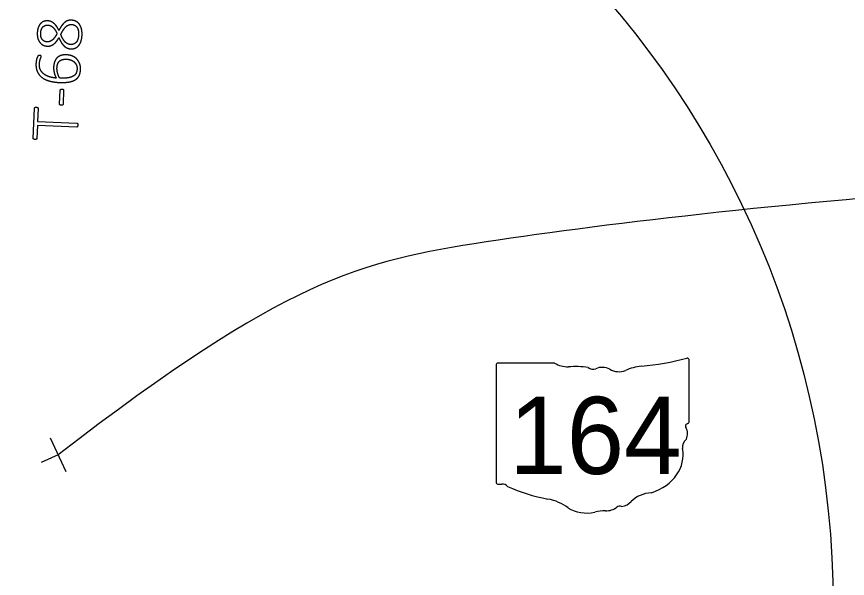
# Model space of a CAD drawing. Extents: x 0 to 1214, y 0 to 883.
# Drawn here: x 200.8 to 281.4, y 330.8 to 385.4 of the extents above; entities that cross this region are included whole.
import ezdxf

# ---------------------------------------------------------------- set-up
doc = ezdxf.new("R2010")
doc.units = 0
for name, color, linetype in [('GM_X_Minor_River', 7, 'Continuous'), ('GM_X_Township_Road_Text', 7, 'Continuous'), ('GM_X_Unincorporated_Location', 7, 'Continuous'), ('SH_Data', 7, 'Continuous')]:
    doc.layers.add(name, color=color, linetype=linetype)

msp = doc.modelspace()

# ---------------------------------------------------------------- linework, layer by layer
at = {"layer": 'GM_X_Minor_River'}
for p, q in [((204.05, 344.481), (205.564, 341.215)), ((204.807, 342.848), (203.174, 342.09))]:
    msp.add_line(p, q, dxfattribs=at)
at = {"layer": 'GM_X_Township_Road_Text'}
for p, q in [((253.012, 351.755), (247.521, 351.755)), ((266.086, 346.082), (266.086, 352.037)), ((247.336, 351.559), (247.336, 340.174)), ((266.084, 346.083), (266.086, 346.082))]:
    msp.add_line(p, q, dxfattribs=at)
for centre, major_axis, start_param, end_param in [((247.551, 351.583), (0.217, 0), 1.712693, 3.28349), ((254.32, 353.076), (2.107, 0), 4.042523, 4.731795), ((259.407, 367.276), (19.884, 0), 4.814394, 5.042369), ((265.878, 352.062), (0.209, 0), 6.141152, 7.989035), ((255.018, 345.363), (7.564, 0), 1.404758, 1.657858), ((256.735, 351.642), (0.608, 0), 3.836095, 5.185415), ((257.627, 350.326), (1.264, 0), 0.950623, 2.079405), ((259.259, 352.131), (1.52, 0), 4.081561, 5.145723), ((261.943, 348.278), (4, 0), 1.699011, 2.107814), ((265.863, 346.059), (0.223, 0), 5.05454, 6.418171), ((266.038, 345.644), (0.323, 0), 1.883978, 3.671073), ((263.983, 344.892), (1.939, 0), 5.934695, 6.695948), ((266.834, 343.589), (1.411, 0), 2.387724, 3.262537), ((260.521, 342.832), (4.973, 0), 5.101752, 6.440018), ((247.553, 340.149), (0.219, 0), 3.00124, 4.508301), ((247.586, 341.314), (1.672, 0), 4.665946, 4.897461), ((247.928, 339.518), (0.603, 0), 0.519207, 1.627899), ((255.542, 349.746), (14.359, 0), 4.195997, 4.488961), ((262.618, 336.978), (2.724, 0), 1.647645, 2.488434), ((251.261, 335.06), (4.493, 0), 0.823519, 1.323587), ((259.167, 339.071), (1.607, 0), 4.937069, 5.64225), ((256.12, 339.461), (2.851, 0), 4.026481, 4.996735), ((257.767, 335.525), (2.342, 0), 1.495662, 1.94098), ((257.975, 338.608), (1.519, 0), 4.691044, 5.507374), ((259.349, 337.506), (0.428, 0), 1.147584, 2.315152)]:
    msp.add_ellipse(centre, major_axis=major_axis, ratio=0.8, start_param=start_param, end_param=end_param, dxfattribs=at)
at = {"layer": 'GM_X_Unincorporated_Location'}
for p, q in [((206.075, 385.079), (206.075, 385.079)), ((203.814, 384.601), (203.814, 384.601)), ((206.114, 384.657), (206.114, 384.657)), ((205.638, 381.71), (205.638, 381.71)), ((205.659, 381.288), (205.659, 381.288)), ((205.183, 378.377), (205.183, 378.377)), ((204.955, 376.916), (205.015, 378.29)), ((205.342, 378.275), (205.282, 376.902)), ((202.39, 373.595), (202.519, 376.526)), ((202.706, 376.619), (202.706, 376.619))]:
    msp.add_line(p, q, dxfattribs=at)
for points in [[(202.874, 376.51), (202.819, 375.245), (206.635, 375.078)], [(206.618, 374.678), (202.802, 374.845), (202.746, 373.579)]]:
    msp.add_lwpolyline(points, dxfattribs=at)
for points in [[(203.421, 384.959), (203.245, 384.894), (203.107, 384.752)], [(203.788, 385.015), (203.598, 385.023), (203.421, 384.959)], [(204.121, 384.941), (203.965, 385.007), (203.788, 385.015)], [(204.413, 384.758), (204.277, 384.875), (204.121, 384.941)], [(205.419, 384.842), (205.274, 384.717), (205.143, 384.527)], [(205.724, 385.027), (205.564, 384.967), (205.419, 384.842)], [(206.075, 385.079), (205.885, 385.087), (205.724, 385.027)], [(206.547, 384.962), (206.343, 385.067), (206.075, 385.079)], [(206.885, 384.668), (206.751, 384.856), (206.547, 384.962)], [(202.883, 384.389), (202.796, 384.168), (202.783, 383.864)], [(203.107, 384.752), (202.97, 384.611), (202.883, 384.389)], [(203.117, 383.813), (203.126, 384.006), (203.178, 384.157)], [(203.178, 384.157), (203.231, 384.308), (203.322, 384.409)], [(203.322, 384.409), (203.413, 384.51), (203.538, 384.559)], [(203.538, 384.559), (203.663, 384.608), (203.814, 384.601)], [(203.814, 384.601), (204.092, 384.589), (204.313, 384.375)], [(204.313, 384.375), (204.535, 384.162), (204.702, 383.776)], [(204.665, 384.472), (204.549, 384.64), (204.413, 384.758)], [(204.88, 384.09), (204.781, 384.305), (204.665, 384.472)], [(205.143, 384.527), (205.012, 384.337), (204.88, 384.09)], [(205.062, 383.692), (205.195, 383.939), (205.312, 384.124)], [(205.312, 384.124), (205.43, 384.309), (205.552, 384.43)], [(205.552, 384.43), (205.674, 384.551), (205.811, 384.608)], [(205.811, 384.608), (205.947, 384.664), (206.114, 384.657)], [(206.114, 384.657), (206.448, 384.642), (206.632, 384.39)], [(206.632, 384.39), (206.816, 384.137), (206.795, 383.665)], [(207.082, 384.214), (207.02, 384.48), (206.885, 384.668)], [(207.13, 383.615), (207.144, 383.949), (207.082, 384.214)], [(202.783, 383.864), (202.769, 383.539), (202.842, 383.296)], [(202.842, 383.296), (202.915, 383.053), (203.051, 382.893)], [(203.269, 383.2), (203.1, 383.416), (203.117, 383.813)], [(203.749, 382.97), (203.438, 382.983), (203.269, 383.2)], [(204.474, 383.407), (204.364, 383.252), (204.25, 383.153)], [(204.702, 383.776), (204.584, 383.561), (204.474, 383.407)], [(204.645, 383.012), (204.77, 383.169), (204.885, 383.378)], [(204.885, 383.378), (204.989, 383.133), (205.103, 382.936)], [(205.269, 383.269), (205.167, 383.451), (205.062, 383.692)], [(205.483, 382.968), (205.37, 383.087), (205.269, 383.269)], [(206.795, 383.665), (206.774, 383.177), (206.569, 382.938)], [(207.038, 383.054), (207.116, 383.303), (207.13, 383.615)], [(203.051, 382.893), (203.186, 382.733), (203.37, 382.649)], [(203.37, 382.649), (203.553, 382.566), (203.759, 382.557)], [(204.013, 383.009), (203.89, 382.964), (203.749, 382.97)], [(203.759, 382.557), (203.933, 382.549), (204.088, 382.598)], [(204.25, 383.153), (204.136, 383.055), (204.013, 383.009)], [(204.088, 382.598), (204.242, 382.647), (204.381, 382.751)], [(204.381, 382.751), (204.52, 382.855), (204.645, 383.012)], [(205.103, 382.936), (205.218, 382.739), (205.356, 382.6)], [(205.356, 382.6), (205.494, 382.461), (205.663, 382.382)], [(205.724, 382.785), (205.596, 382.848), (205.483, 382.968)], [(205.663, 382.382), (205.832, 382.302), (206.042, 382.293)], [(206.013, 382.715), (205.853, 382.722), (205.724, 382.785)], [(206.569, 382.938), (206.363, 382.699), (206.013, 382.715)], [(206.042, 382.293), (206.29, 382.282), (206.486, 382.37)], [(206.486, 382.37), (206.682, 382.459), (206.821, 382.632)], [(206.821, 382.632), (206.96, 382.804), (207.038, 383.054)], [(202.841, 381.589), (202.822, 381.567), (202.789, 381.498)], [(202.879, 381.621), (202.86, 381.612), (202.841, 381.589)], [(202.917, 381.635), (202.897, 381.63), (202.879, 381.621)], [(202.962, 381.643), (202.937, 381.641), (202.917, 381.635)], [(203.02, 381.644), (202.987, 381.645), (202.962, 381.643)], [(203.085, 381.639), (203.056, 381.642), (203.02, 381.644)], [(203.134, 381.628), (203.115, 381.637), (203.085, 381.639)], [(203.164, 381.602), (203.153, 381.618), (203.134, 381.628)], [(203.147, 381.463), (203.172, 381.523), (203.174, 381.559)], [(203.174, 381.559), (203.175, 381.585), (203.164, 381.602)], [(205.165, 381.67), (204.941, 381.619), (204.769, 381.482)], [(205.638, 381.71), (205.389, 381.721), (205.165, 381.67)], [(206.142, 381.609), (205.894, 381.699), (205.638, 381.71)], [(206.582, 381.341), (206.391, 381.519), (206.142, 381.609)], [(202.656, 380.863), (202.641, 380.519), (202.723, 380.253)], [(202.681, 381.104), (202.661, 380.984), (202.656, 380.863)], [(202.729, 381.327), (202.701, 381.225), (202.681, 381.104)], [(202.789, 381.498), (202.757, 381.429), (202.729, 381.327)], [(203.102, 380.226), (202.975, 380.469), (202.99, 380.799)], [(202.99, 380.799), (202.997, 380.973), (203.026, 381.099)], [(203.026, 381.099), (203.054, 381.226), (203.088, 381.315)], [(203.088, 381.315), (203.121, 381.403), (203.147, 381.463)], [(204.492, 381.111), (204.387, 380.876), (204.371, 380.519)], [(204.769, 381.482), (204.598, 381.345), (204.492, 381.111)], [(204.697, 380.455), (204.708, 380.704), (204.782, 380.87)], [(204.782, 380.87), (204.857, 381.035), (204.982, 381.131)], [(204.982, 381.131), (205.108, 381.227), (205.281, 381.262)], [(205.281, 381.262), (205.453, 381.297), (205.659, 381.288)], [(205.659, 381.288), (205.837, 381.281), (206.016, 381.219)], [(206.016, 381.219), (206.196, 381.157), (206.34, 381.036)], [(206.34, 381.036), (206.484, 380.915), (206.57, 380.734)], [(206.886, 380.889), (206.773, 381.162), (206.582, 381.341)], [(206.982, 380.241), (206.999, 380.617), (206.886, 380.889)], [(202.723, 380.253), (202.805, 379.987), (202.959, 379.787)], [(203.455, 379.818), (203.229, 379.982), (203.102, 380.226)], [(204.371, 380.519), (204.364, 380.352), (204.383, 380.201)], [(204.383, 380.201), (204.403, 380.049), (204.438, 379.913)], [(204.709, 380.178), (204.691, 380.318), (204.697, 380.455)], [(204.765, 379.907), (204.728, 380.038), (204.709, 380.178)], [(206.645, 380.311), (206.635, 380.079), (206.544, 379.908)], [(206.57, 380.734), (206.656, 380.553), (206.645, 380.311)], [(206.899, 379.802), (206.971, 379.992), (206.982, 380.241)], [(202.959, 379.787), (203.112, 379.587), (203.33, 379.448)], [(203.33, 379.448), (203.547, 379.309), (203.801, 379.219)], [(203.982, 379.566), (203.681, 379.654), (203.455, 379.818)], [(203.801, 379.219), (204.054, 379.129), (204.336, 379.084)], [(204.617, 379.453), (204.283, 379.477), (203.982, 379.566)], [(204.438, 379.913), (204.473, 379.777), (204.521, 379.662)], [(204.521, 379.662), (204.568, 379.547), (204.617, 379.453)], [(204.854, 379.657), (204.802, 379.776), (204.765, 379.907)], [(204.968, 379.444), (204.906, 379.539), (204.854, 379.657)], [(205.743, 379.471), (205.427, 379.424), (204.968, 379.444)], [(206.255, 379.627), (206.058, 379.518), (205.743, 379.471)], [(205.987, 379.097), (206.216, 379.149), (206.395, 379.24)], [(206.544, 379.908), (206.452, 379.736), (206.255, 379.627)], [(206.395, 379.24), (206.575, 379.331), (206.701, 379.471)], [(206.701, 379.471), (206.827, 379.611), (206.899, 379.802)], [(204.336, 379.084), (204.618, 379.039), (204.9, 379.027)], [(204.9, 379.027), (205.215, 379.013), (205.486, 379.029)], [(205.015, 378.29), (205.016, 378.309), (205.024, 378.327)], [(205.024, 378.327), (205.033, 378.345), (205.054, 378.357)], [(205.054, 378.357), (205.074, 378.369), (205.105, 378.374)], [(205.105, 378.374), (205.137, 378.379), (205.183, 378.377)], [(205.183, 378.377), (205.278, 378.373), (205.311, 378.346)], [(205.311, 378.346), (205.344, 378.318), (205.342, 378.275)], [(205.486, 379.029), (205.758, 379.045), (205.987, 379.097)], [(204.988, 376.844), (204.953, 376.873), (204.955, 376.916)], [(205.114, 376.81), (205.022, 376.814), (204.988, 376.844)], [(205.243, 376.833), (205.206, 376.806), (205.114, 376.81)], [(205.282, 376.902), (205.281, 376.859), (205.243, 376.833)], [(202.519, 376.526), (202.52, 376.549), (202.532, 376.568)], [(202.532, 376.568), (202.544, 376.587), (202.567, 376.599)], [(202.567, 376.599), (202.591, 376.611), (202.625, 376.616)], [(202.625, 376.616), (202.66, 376.621), (202.706, 376.619)], [(202.706, 376.619), (202.748, 376.617), (202.781, 376.609)], [(202.781, 376.609), (202.813, 376.601), (202.834, 376.587)], [(202.834, 376.587), (202.854, 376.573), (202.865, 376.553)], [(202.865, 376.553), (202.875, 376.533), (202.874, 376.51)], [(206.654, 374.686), (206.638, 374.677), (206.618, 374.678)], [(206.635, 375.078), (206.655, 375.077), (206.671, 375.066)], [(206.682, 374.718), (206.671, 374.695), (206.654, 374.686)], [(206.671, 375.066), (206.687, 375.056), (206.696, 375.033)], [(206.701, 374.779), (206.693, 374.74), (206.682, 374.718)], [(206.696, 375.033), (206.705, 375.009), (206.709, 374.97)], [(206.712, 374.874), (206.709, 374.819), (206.701, 374.779)], [(206.709, 374.97), (206.714, 374.93), (206.712, 374.874)], [(202.4, 373.55), (202.389, 373.569), (202.39, 373.595)], [(202.433, 373.517), (202.411, 373.532), (202.4, 373.55)], [(202.489, 373.495), (202.455, 373.503), (202.433, 373.517)], [(202.569, 373.485), (202.523, 373.487), (202.489, 373.495)], [(202.644, 373.489), (202.611, 373.483), (202.569, 373.485)], [(202.699, 373.506), (202.677, 373.494), (202.644, 373.489)], [(202.733, 373.536), (202.721, 373.518), (202.699, 373.506)], [(202.746, 373.579), (202.745, 373.553), (202.733, 373.536)]]:
    msp.add_open_spline(points, degree=2, dxfattribs=at)
at = {"layer": 'SH_Data'}
msp.add_circle((190.05, 328.189), 90, dxfattribs=at)
msp.add_open_spline([(299.429, 369.092), (276.512, 367.462), (240.977, 363.364), (226.99, 359.915), (204.807, 342.848)], degree=3, dxfattribs=at)

# ---------------------------------------------------------------- texts
at = {"layer": 'GM_X_Township_Road_Text'}
msp.add_text('164', height=7.5, dxfattribs=at).set_placement((248.605, 340.977))

doc.saveas('drawing.dxf')
